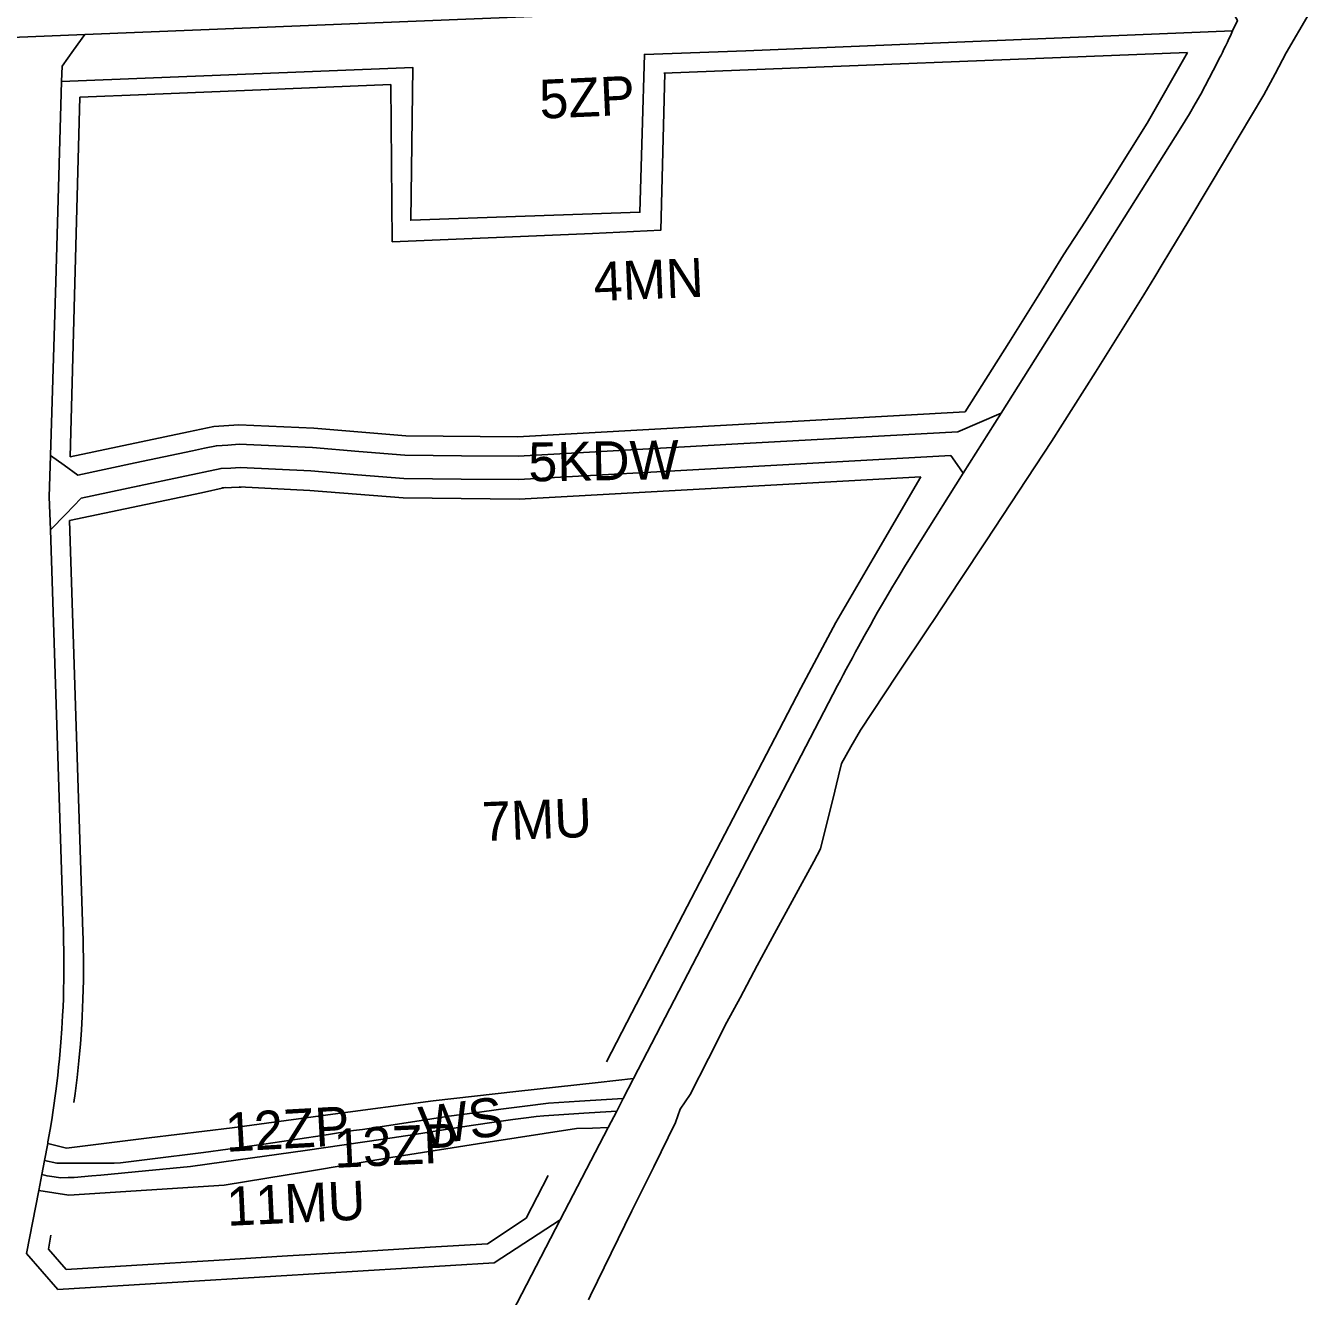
# Model space of a CAD drawing. Extents: x 7418021 to 7419743, y 5540231 to 5541685.
# Drawn here: x 7419339.9 to 7419669.6, y 5540517.9 to 5540844.3 of the extents above; entities that cross this region are included whole.
import ezdxf

# ---------------------------------------------------------------- set-up
doc = ezdxf.new("R2010")
doc.units = 0
for name, color, linetype in [('linie_rozgraniczajace', 7, 'Continuous'), ('linie_zabudowy_nieprzekraczalne', 7, 'Continuous'), ('linie_zabudowy_obowiazujace', 7, 'Continuous'), ('oznaczenia_przeznaczen', 7, 'Continuous')]:
    doc.layers.add(name, color=color, linetype=linetype)

msp = doc.modelspace()

# ---------------------------------------------------------------- linework, layer by layer
at = {"layer": 'linie_rozgraniczajace'}
for points in [[(7419646.42, 5540853.87), (7419469.94, 5540846.7), (7419355.09, 5540842.04), (7419331.92, 5540841.1)], [(7419669.56, 5540847.51), (7419663.65, 5540837.34), (7419660.77, 5540831.97), (7419657.89, 5540826.59), (7419648.37, 5540810.63), (7419648.25, 5540810.44), (7419638.61, 5540794.28), (7419633.73, 5540786.2), (7419631.8, 5540783.02), (7419629.88, 5540779.85), (7419627.06, 5540775.18), (7419614.61, 5540755.32), (7419603.33, 5540737.5), (7419594.93, 5540724.76), (7419586.54, 5540712.03), (7419579.78, 5540701.8), (7419573.03, 5540691.56), (7419572.07, 5540690.12), (7419563.65, 5540677.46), (7419554.27, 5540663.35), (7419551.83, 5540659.08), (7419549.4, 5540654.81), (7419548.62, 5540651.6), (7419547.15, 5540645.56), (7419546.33, 5540642.23)], [(7419461.14, 5540506.63), (7419477.19, 5540537.56), (7419489.49, 5540561.27), (7419491.67, 5540565.48), (7419493.35, 5540568.72), (7419496.02, 5540573.86), (7419548.41, 5540674.83), (7419549.14, 5540676.22), (7419549.86, 5540677.61), (7419550.63, 5540679.06), (7419552.19, 5540681.98), (7419552.98, 5540683.44), (7419553.76, 5540684.87), (7419555.23, 5540687.53), (7419556.82, 5540690.37), (7419557.72, 5540691.96), (7419558.69, 5540693.66), (7419559.67, 5540695.36), (7419560.76, 5540697.25), (7419562.35, 5540699.95), (7419564.18, 5540703), (7419565.85, 5540705.75), (7419566.86, 5540707.4), (7419568.24, 5540709.64), (7419568.92, 5540710.72), (7419569.78, 5540712.09), (7419580.66, 5540729.34), (7419590.4, 5540744.77), (7419602.07, 5540763.27), (7419636.56, 5540818.07), (7419638.76, 5540821.69), (7419640.21, 5540824.24), (7419641.66, 5540826.78), (7419642.79, 5540828.88), (7419644.88, 5540832.81), (7419645.83, 5540834.65), (7419646.53, 5540836.04), (7419646.82, 5540836.61), (7419647.23, 5540837.44), (7419647.63, 5540838.28), (7419648.04, 5540839.11), (7419648.27, 5540839.61), (7419648.51, 5540840.11), (7419648.92, 5540840.96), (7419649.2, 5540841.55), (7419649.48, 5540842.14), (7419649.87, 5540842.99), (7419651.11, 5540845.7)], [(7419331.92, 5540841.1), (7419355.09, 5540842.04), (7419352.15, 5540838.02), (7419349.21, 5540833.97), (7419349.1, 5540829.96), (7419347.58, 5540778.52), (7419346.27, 5540733.88), (7419345.87, 5540723.33), (7419346.22, 5540714.81), (7419347.76, 5540667.29), (7419349.56, 5540611.51), (7419349.7, 5540604.28), (7419349.69, 5540601.74), (7419349.67, 5540599.21), (7419349.62, 5540596.83), (7419349.56, 5540594.46), (7419349.46, 5540592.26), (7419349.37, 5540590.06), (7419349.27, 5540588.35), (7419349.17, 5540586.64), (7419348.93, 5540583.18), (7419348.74, 5540581.04), (7419348.55, 5540578.9), (7419348.33, 5540576.78), (7419348.11, 5540574.66), (7419347.63, 5540570.64), (7419346.95, 5540565.72), (7419346.56, 5540563.24), (7419346.17, 5540560.76), (7419345.59, 5540557.58), (7419345.52, 5540557.18), (7419344.7, 5540552.79), (7419344, 5540549.17), (7419343.21, 5540545.11), (7419340.05, 5540528.89), (7419344.09, 5540524.29), (7419348.13, 5540519.68), (7419404.15, 5540523.08), (7419460.17, 5540526.48), (7419477.19, 5540537.56), (7419461.14, 5540506.63)], [(7419546.33, 5540642.23), (7419544.05, 5540632.86), (7419542.27, 5540629.62), (7419537.23, 5540620.36), (7419532.19, 5540611.1), (7419527.77, 5540602.86), (7419523.35, 5540594.61), (7419519.98, 5540588.33), (7419515.27, 5540579.05), (7419510.55, 5540569.77), (7419507.98, 5540566.01), (7419506.77, 5540562.57), (7419501.17, 5540551.21), (7419495.56, 5540539.86), (7419490.25, 5540528.97), (7419484.95, 5540518.09), (7419484.45, 5540516.98)]]:
    msp.add_lwpolyline(points, dxfattribs=at)
for points in [[(7419355.09, 5540842.04), (7419469.94, 5540846.7), (7419646.42, 5540853.87), (7419651.11, 5540845.7), (7419649.87, 5540842.99), (7419587.34, 5540840.46), (7419524.8, 5540837.92), (7419498.8, 5540836.95), (7419498.21, 5540816.69), (7419497.63, 5540796.42), (7419468.2, 5540795.38), (7419438.78, 5540794.34), (7419439.03, 5540813.98), (7419439.29, 5540833.62), (7419394.19, 5540831.79), (7419349.1, 5540829.96), (7419349.21, 5540833.97), (7419352.15, 5540838.02)], [(7419439.29, 5540833.62), (7419439.03, 5540813.98), (7419438.78, 5540794.34), (7419468.2, 5540795.38), (7419497.63, 5540796.42), (7419498.21, 5540816.69), (7419498.8, 5540836.95), (7419524.8, 5540837.92), (7419587.34, 5540840.46), (7419649.87, 5540842.99), (7419649.48, 5540842.14), (7419649.2, 5540841.55), (7419648.92, 5540840.96), (7419648.51, 5540840.11), (7419648.27, 5540839.61), (7419648.04, 5540839.11), (7419647.63, 5540838.28), (7419647.23, 5540837.44), (7419646.82, 5540836.61), (7419646.53, 5540836.04), (7419645.83, 5540834.65), (7419644.88, 5540832.81), (7419642.79, 5540828.88), (7419641.66, 5540826.78), (7419640.21, 5540824.24), (7419638.76, 5540821.69), (7419636.56, 5540818.07), (7419602.07, 5540763.27), (7419590.4, 5540744.77), (7419584.84, 5540742.4), (7419579.29, 5540740.03), (7419522.81, 5540736.88), (7419466.33, 5540733.73), (7419451.81, 5540733.86), (7419437.29, 5540734), (7419425.42, 5540734.97), (7419413.55, 5540735.94), (7419404.13, 5540736.37), (7419394.72, 5540736.79), (7419391.8, 5540736.61), (7419388.86, 5540736.42), (7419385.8, 5540735.78), (7419382.73, 5540735.13), (7419368, 5540732.02), (7419353.27, 5540728.91), (7419349.77, 5540731.4), (7419346.27, 5540733.88), (7419347.58, 5540778.52), (7419349.1, 5540829.96), (7419394.19, 5540831.79)], [(7419590.4, 5540744.77), (7419580.66, 5540729.34), (7419579.07, 5540731.63), (7419577.47, 5540733.92), (7419521.97, 5540730.82), (7419466.46, 5540727.72), (7419451.74, 5540727.86), (7419437.02, 5540728), (7419425.08, 5540728.98), (7419413.15, 5540729.95), (7419404.05, 5540730.42), (7419394.94, 5540730.88), (7419392.53, 5540730.7), (7419390.07, 5540730.6), (7419369.06, 5540726.11), (7419354.15, 5540722.97), (7419350.19, 5540718.89), (7419346.22, 5540714.81), (7419345.87, 5540723.33), (7419346.27, 5540733.88), (7419349.77, 5540731.4), (7419353.27, 5540728.91), (7419368, 5540732.02), (7419382.73, 5540735.13), (7419385.8, 5540735.78), (7419388.86, 5540736.42), (7419391.8, 5540736.61), (7419394.72, 5540736.79), (7419404.13, 5540736.37), (7419413.55, 5540735.94), (7419425.42, 5540734.97), (7419437.29, 5540734), (7419451.81, 5540733.86), (7419466.33, 5540733.73), (7419522.81, 5540736.88), (7419579.29, 5540740.03), (7419584.84, 5540742.4)], [(7419346.22, 5540714.81), (7419350.19, 5540718.89), (7419354.15, 5540722.97), (7419369.06, 5540726.11), (7419390.07, 5540730.6), (7419392.53, 5540730.7), (7419394.94, 5540730.88), (7419404.05, 5540730.42), (7419413.15, 5540729.95), (7419425.08, 5540728.98), (7419437.02, 5540728), (7419451.74, 5540727.86), (7419466.46, 5540727.72), (7419521.97, 5540730.82), (7419577.47, 5540733.92), (7419579.07, 5540731.63), (7419580.66, 5540729.34), (7419569.78, 5540712.09), (7419568.92, 5540710.72), (7419568.24, 5540709.64), (7419566.86, 5540707.4), (7419565.85, 5540705.75), (7419564.18, 5540703), (7419562.35, 5540699.95), (7419560.76, 5540697.25), (7419559.67, 5540695.36), (7419558.69, 5540693.66), (7419557.72, 5540691.96), (7419556.82, 5540690.37), (7419555.23, 5540687.53), (7419553.76, 5540684.87), (7419552.98, 5540683.44), (7419552.19, 5540681.98), (7419550.63, 5540679.06), (7419549.86, 5540677.61), (7419549.14, 5540676.22), (7419548.41, 5540674.83), (7419496.02, 5540573.86), (7419486.95, 5540572.85), (7419465.76, 5540570.49), (7419444.57, 5540568.13), (7419418.73, 5540564.68), (7419392.9, 5540561.23), (7419371.63, 5540558.62), (7419350.36, 5540556.01), (7419347.94, 5540556.6), (7419345.52, 5540557.18), (7419345.59, 5540557.58), (7419346.17, 5540560.76), (7419346.56, 5540563.24), (7419346.95, 5540565.72), (7419347.63, 5540570.64), (7419348.11, 5540574.66), (7419348.33, 5540576.78), (7419348.55, 5540578.9), (7419348.74, 5540581.04), (7419348.93, 5540583.18), (7419349.17, 5540586.64), (7419349.27, 5540588.35), (7419349.37, 5540590.06), (7419349.46, 5540592.26), (7419349.56, 5540594.46), (7419349.62, 5540596.83), (7419349.67, 5540599.21), (7419349.69, 5540601.74), (7419349.7, 5540604.28), (7419349.56, 5540611.51), (7419347.76, 5540667.29)], [(7419496.02, 5540573.86), (7419493.35, 5540568.72), (7419489.06, 5540568.49), (7419482.11, 5540568.05), (7419474.17, 5540567.52), (7419468.06, 5540566.75), (7419461.95, 5540565.98), (7419455.26, 5540565.08), (7419448.58, 5540564.17), (7419441.42, 5540563.09), (7419434.26, 5540562.01), (7419430.3, 5540561.41), (7419426.35, 5540560.81), (7419424.07, 5540560.47), (7419421.8, 5540560.13), (7419416.04, 5540559.25), (7419410.27, 5540558.38), (7419401.03, 5540557.03), (7419391.78, 5540555.69), (7419385.53, 5540554.83), (7419371.74, 5540553.11), (7419364.19, 5540552.24), (7419362.64, 5540552.11), (7419359.67, 5540552.12), (7419356.7, 5540552.13), (7419354.29, 5540552.13), (7419351.89, 5540552.14), (7419349.89, 5540552.15), (7419347.9, 5540552.15), (7419344.7, 5540552.79), (7419345.52, 5540557.18), (7419347.94, 5540556.6), (7419350.36, 5540556.01), (7419371.63, 5540558.62), (7419392.9, 5540561.23), (7419418.73, 5540564.68), (7419444.57, 5540568.13), (7419465.76, 5540570.49), (7419486.95, 5540572.85)], [(7419493.35, 5540568.72), (7419491.67, 5540565.48), (7419487.44, 5540565.21), (7419483.21, 5540564.93), (7419478.06, 5540564.6), (7419472.91, 5540564.26), (7419471.02, 5540564.07), (7419469.13, 5540563.87), (7419464.98, 5540563.32), (7419460.83, 5540562.76), (7419454.26, 5540561.76), (7419447.7, 5540560.75), (7419439.71, 5540559.51), (7419431.72, 5540558.27), (7419421.69, 5540556.81), (7419411.66, 5540555.35), (7419401.2, 5540553.9), (7419390.74, 5540552.45), (7419382.21, 5540551.26), (7419370.68, 5540550.17), (7419359.15, 5540549.07), (7419356.89, 5540548.87), (7419352.33, 5540548.43), (7419350.78, 5540548.41), (7419348.75, 5540548.39), (7419348.28, 5540548.45), (7419346.6, 5540548.67), (7419345.39, 5540548.83), (7419344, 5540549.17), (7419344.7, 5540552.79), (7419347.9, 5540552.15), (7419349.89, 5540552.15), (7419351.89, 5540552.14), (7419354.29, 5540552.13), (7419356.7, 5540552.13), (7419359.67, 5540552.12), (7419362.64, 5540552.11), (7419364.19, 5540552.24), (7419371.74, 5540553.11), (7419385.53, 5540554.83), (7419391.78, 5540555.69), (7419401.03, 5540557.03), (7419410.27, 5540558.38), (7419416.04, 5540559.25), (7419421.8, 5540560.13), (7419424.07, 5540560.47), (7419426.35, 5540560.81), (7419430.3, 5540561.41), (7419434.26, 5540562.01), (7419441.42, 5540563.09), (7419448.58, 5540564.17), (7419455.26, 5540565.08), (7419461.95, 5540565.98), (7419468.06, 5540566.75), (7419474.17, 5540567.52), (7419482.11, 5540568.05), (7419489.06, 5540568.49)], [(7419491.67, 5540565.48), (7419489.49, 5540561.27), (7419485.43, 5540561.15), (7419481.38, 5540561.04), (7419457.54, 5540557.31), (7419433.69, 5540553.59), (7419412.26, 5540550.01), (7419390.83, 5540546.43), (7419370.89, 5540545.15), (7419350.95, 5540543.88), (7419347.08, 5540544.49), (7419343.21, 5540545.11), (7419344, 5540549.17), (7419345.39, 5540548.83), (7419346.6, 5540548.67), (7419348.28, 5540548.45), (7419348.75, 5540548.39), (7419350.78, 5540548.41), (7419352.33, 5540548.43), (7419356.89, 5540548.87), (7419359.15, 5540549.07), (7419370.68, 5540550.17), (7419382.21, 5540551.26), (7419390.74, 5540552.45), (7419401.2, 5540553.9), (7419411.66, 5540555.35), (7419421.69, 5540556.81), (7419431.72, 5540558.27), (7419439.71, 5540559.51), (7419447.7, 5540560.75), (7419454.26, 5540561.76), (7419460.83, 5540562.76), (7419464.98, 5540563.32), (7419469.13, 5540563.87), (7419471.02, 5540564.07), (7419472.91, 5540564.26), (7419478.06, 5540564.6), (7419483.21, 5540564.93), (7419487.44, 5540565.21)], [(7419343.21, 5540545.11), (7419347.08, 5540544.49), (7419350.95, 5540543.88), (7419370.89, 5540545.15), (7419390.83, 5540546.43), (7419412.26, 5540550.01), (7419433.69, 5540553.59), (7419457.54, 5540557.31), (7419481.38, 5540561.04), (7419485.43, 5540561.15), (7419489.49, 5540561.27), (7419477.19, 5540537.56), (7419460.17, 5540526.48), (7419404.15, 5540523.08), (7419348.13, 5540519.68), (7419344.09, 5540524.29), (7419340.05, 5540528.89)]]:
    msp.add_lwpolyline(points, close=True, dxfattribs=at)
at = {"layer": 'linie_zabudowy_nieprzekraczalne'}
for points in [[(7419627.94, 5540819.29), (7419638.31, 5540837.41)], [(7419353.8, 5540826), (7419351.27, 5540733.6)], [(7419618.97, 5540805.04), (7419627.94, 5540819.29)], [(7419612.07, 5540794.11), (7419618.97, 5540805.04)], [(7419606.46, 5540785.51), (7419612.07, 5540794.11)], [(7419600.12, 5540775.17), (7419606.46, 5540785.51)], [(7419592.38, 5540762.9), (7419600.12, 5540775.17)], [(7419581.18, 5540745.14), (7419592.38, 5540762.9)], [(7419466.21, 5540738.73), (7419581.18, 5540745.14)], [(7419381.7, 5540740.02), (7419388.16, 5540741.39)], [(7419388.16, 5540741.39), (7419394.65, 5540741.8)], [(7419394.65, 5540741.8), (7419413.87, 5540740.93)], [(7419413.87, 5540740.93), (7419437.52, 5540739)], [(7419351.27, 5540733.6), (7419381.7, 5540740.02)], [(7419437.52, 5540739), (7419466.21, 5540738.73)], [(7419569.77, 5540728.48), (7419466.58, 5540722.73)], [(7419557.54, 5540707.48), (7419569.77, 5540728.48)], [(7419385, 5540724.37), (7419351.15, 5540717.22)], [(7419391.15, 5540725.67), (7419385, 5540724.37)], [(7419390.28, 5540725.61), (7419395.19, 5540725.81)], [(7419412.82, 5540724.97), (7419394.69, 5540725.89)], [(7419436.79, 5540723.01), (7419412.82, 5540724.97)], [(7419466.58, 5540722.73), (7419436.79, 5540723.01)], [(7419351.15, 5540717.22), (7419354.57, 5540611.5)], [(7419547.95, 5540691.01), (7419557.54, 5540707.48)], [(7419538.93, 5540674.18), (7419547.95, 5540691.01)], [(7419532.24, 5540661.31), (7419538.93, 5540674.18)], [(7419513.03, 5540624.31), (7419532.24, 5540661.31)], [(7419495.58, 5540590.71), (7419513.03, 5540624.31)], [(7419354.56, 5540611.66), (7419354.63, 5540609.48)], [(7419354.63, 5540609.48), (7419354.66, 5540607.96)], [(7419354.66, 5540607.96), (7419354.7, 5540604.3)], [(7419354.7, 5540604.3), (7419354.68, 5540599.14)], [(7419354.68, 5540599.14), (7419354.56, 5540594.29)], [(7419354.56, 5540594.29), (7419354.37, 5540589.81)], [(7419354.37, 5540589.81), (7419354.17, 5540586.32)], [(7419489.06, 5540578.16), (7419495.58, 5540590.71)], [(7419354.17, 5540586.32), (7419353.91, 5540582.79)], [(7419353.91, 5540582.79), (7419353.53, 5540578.42)], [(7419353.53, 5540578.42), (7419353.09, 5540574.1)], [(7419353.09, 5540574.1), (7419352.59, 5540570)], [(7419352.59, 5540570), (7419352.27, 5540567.68)], [(7419468.41, 5540538.02), (7419474.09, 5540548.96)], [(7419458.46, 5540531.39), (7419468.41, 5540538.02)], [(7419346.3, 5540533.66), (7419345.72, 5540530.01)], [(7419345.72, 5540530.01), (7419350.27, 5540524.82)], [(7419423.53, 5540529.27), (7419443.79, 5540530.5)], [(7419443.79, 5540530.5), (7419458.46, 5540531.39)], [(7419367.02, 5540525.84), (7419389.54, 5540527.21)], [(7419389.54, 5540527.21), (7419407.14, 5540528.28)], [(7419407.14, 5540528.28), (7419423.53, 5540529.27)], [(7419350.27, 5540524.82), (7419367.02, 5540525.84)]]:
    msp.add_lwpolyline(points, dxfattribs=at)
at = {"layer": 'linie_zabudowy_obowiazujace'}
for points in [[(7419638.31, 5540837.41), (7419503.75, 5540832.11)], [(7419504.02, 5540832.12), (7419502.99, 5540791.8), (7419485.41, 5540790.94), (7419434.04, 5540788.82), (7419433.62, 5540829.24)], [(7419433.62, 5540829.24), (7419370.98, 5540826.7), (7419353.8, 5540826)]]:
    msp.add_lwpolyline(points, dxfattribs=at)

# ---------------------------------------------------------------- texts
at = {"layer": 'oznaczenia_przeznaczen'}
for s, rotation, p in [('5ZP', 2.5711, (7419472.02, 5540820.42)), ('4MN', 2.396, (7419485.94, 5540773.55)), ('5KDW', 0.9412, (7419469.05, 5540727.24)), ('7MU', 2.2595, (7419457.26, 5540634.86)), ('WS', 7.595, (7419441.72, 5540556.57)), ('12ZP', 3.2408, (7419391.4, 5540555.01)), ('13ZP', 2.669, (7419419.23, 5540550.9)), ('11MU', 2.6921, (7419391.69, 5540536))]:
    msp.add_text(s, height=10, rotation=rotation, dxfattribs=at).set_placement(p)

doc.saveas('drawing.dxf')
